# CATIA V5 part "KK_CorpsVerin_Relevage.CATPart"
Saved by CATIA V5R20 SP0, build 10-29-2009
Part number: Corps verin de relevage
Bounding box of the stored display mesh (mm): x -382.24 to -170.906, y -95.994 to 95.994, z -673.525 to 575.99
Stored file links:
  G:\Khaled_CFAO_2011\ST2M\ST2M_GR2\aboulegue\Khaled\CAD_thinkMOTION\KK_CorpsVerin_Relevage.CATPart
  G:\Khaled_CFAO_2011\ST2M\ST2M_GR2\aboulegue\Khaled\CAD_thinkMOTION\KK_Train_Atterrissage.CATProduct
  G:\Khaled_CFAO_2011\ST2M\ST2M_GR2\aboulegue\Khaled\CAD_thinkMOTION\KK_SqueletteVerin_Relevage.CATPart
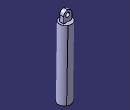
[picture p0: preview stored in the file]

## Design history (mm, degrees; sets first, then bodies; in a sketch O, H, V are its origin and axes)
External parameters (linked from other documents)
  `External.Longueur corps de verin de relevage` = 1184 mm
  `External.Longueur tige verin de relevage` = 960 mm
Set1
  Plane1: linked copy from another document
  Line1: linked copy from another document
  Point1 "Point.19": linked copy from another document
  Line2: linked copy from another document
  Point2 "Point.11": linked copy from another document
Body1 (main body)
  Sketch1 on Plane1, origin (-278.7682, 0, -4.978), H (0, 1, 0), V (-0.0179, 0, 0.9998)
  Sketch2 on Plane1, origin (-278.7682, 0, -4.978), H (0, 1, 0), V (-0.0179, 0, 0.9998)
    line L1 (0, 421.0604) -> (96, 421.0604)
    line L2 (96, 421.0604) -> (96, -666.9396)
    line L3 (96, -666.9396) -> (0, -666.9396)
    line L4 (0, -666.9396) -> (0, 421.0604)
    point P4 (0, -666.9396)
    reference projected line E1 (0, 517.0604) -> (0, -762.9396) from Line1
    reference projected point E2 (0, -666.9396) from Point1
    length L2 = 1088 {= `External.Longueur corps de verin de relevage` -96mm}
    length L1 = 96
    horizontal: L1 H, L3 H
    vertical: L2 V, L4 V
    coincidence: L4 E1, P4 E2
  Shaft1: profile Sketch2, axis Line1, angle 360
  Sketch3 on face of Shaft1 from Sketch2.L1, origin (-7.5177, 0, 420.9933), H (0, -1, 0), V (0.9998, 0, 0.0179)
    line L1 (-32, -214.8127) -> (32, -214.8127)
    line L2 (32, -214.8127) -> (32, -342.8127)
    line L3 (32, -342.8127) -> (-32, -342.8127)
    line L4 (-32, -342.8127) -> (-32, -214.8127)
    reference projected line E1 (200, -278.8127) -> (-200, -278.8127) from Line2
    reference projected point E2 (0, -278.8127) from Line1
    length L2 = 128
    length L1 = 64
    distance E1 L3 = 64
    distance E2 L4 = 32
    horizontal: L1 H, L3 H
    vertical: L2 V, L4 V
  Pad1: profile Sketch3, direction (-0.0179, 0, 0.9998), length 160
  Sketch4 on face of Shaft1 from Sketch2.L3, origin (11.9077, 0, -666.8333), H (0, 1, 0), V (0.9998, 0, 0.0179)
    circle A1 centre (0, -278.8127) radius 48
    reference projected circle E1 centre (0, -278.8127) radius 96 from edge [face of Shaft1 from Sketch2.L2 | face of Shaft1 from Sketch2.L3]
    radius A1 = 48
    concentricity: A1 E1
  Pocket1: profile Sketch4, direction (-0.0179, 0, 0.9998), length 960 {= `External.Longueur tige verin de relevage`}
  Fillet1: radius 64, on edge [face of Pad1 from Sketch3.L3 | end face of Pad1]; edge [face of Pad1 from Sketch3.L1 | end face of Pad1]
  Sketch5 on face of Pad1 from Sketch3.L2, origin (0, -32, 0), H (1, 0, 0), V (0, 0, 1)
    circle A1 centre (-288, 512) radius 32
    point P1 (-288, 512)
    reference projected point E1 (-288, 512) from Point2
    radius A1 = 32
    coincidence: P1 E1
  Pocket2: profile Sketch5, direction (0, 1, 0), through (limit type 6)
  Sketch6 on face of Pad1 from Sketch3.L2, origin (0, -32, 0), H (1, 0, 0), V (0, 0, 1)
    circle A1 centre (-288, 512) radius 48
    point P1 (-288, 512)
    reference projected point E1 (-288, 512) from Point2
    radius A1 = 48
    coincidence: E1 P1
  Pad2: profile Sketch6, direction (0, -1, 0), length 15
